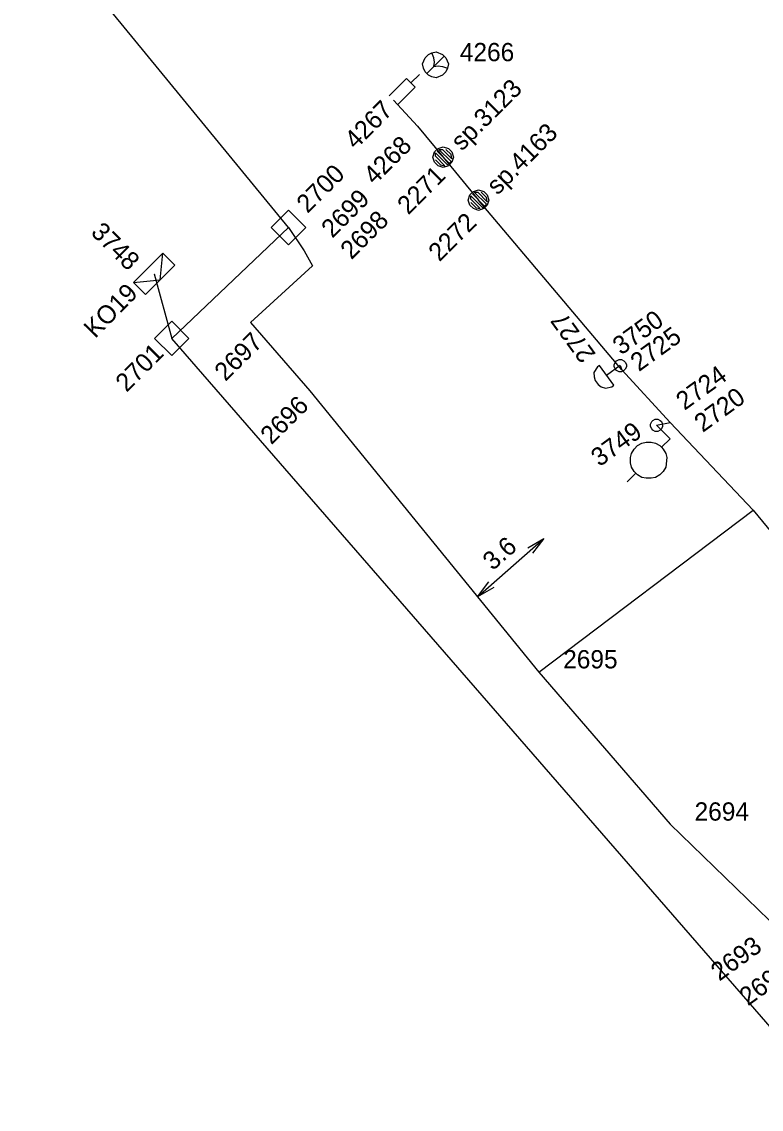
# Model space of a CAD drawing. Extents: x -535557 to -534097, y -1142175 to -1136716.
# Drawn here: x -535102.29 to -535071.96, y -1138807.65 to -1138763 of the extents above; entities that cross this region are included whole.
import ezdxf

# ---------------------------------------------------------------- set-up
doc = ezdxf.new("R2010")
doc.units = 0
doc.layers.add('Default', color=7, linetype='Continuous')
doc.layers.add('SS_SZDC', color=7, linetype='Continuous')

# ---------------------------------------------------------------- blocks, each defined once
blk = doc.blocks.new('POINT_DISPLAY')
at = {"layer": 'Default'}
blk.add_line((0, 0), (0, 0), dxfattribs=at)

msp = doc.modelspace()

# ---------------------------------------------------------------- linework, layer by layer
at = {"layer": 'SS_SZDC'}
for p, q in [((-535091.35, -1138771.45), (-535102.289, -1138758.09)), ((-535085.461, -1138764.275), (-535085.284, -1138764.239)), ((-535085.284, -1138764.239), (-535085.037, -1138764.345)), ((-535085.85, -1138764.734), (-535085.744, -1138764.487)), ((-535085.744, -1138764.487), (-535085.602, -1138764.345)), ((-535084.966, -1138764.416), (-535085.673, -1138765.123)), ((-535085.602, -1138764.345), (-535085.461, -1138764.275)), ((-535085.39, -1138764.487), (-535085.461, -1138764.275)), ((-535085.355, -1138764.663), (-535085.39, -1138764.487)), ((-535085.39, -1138764.84), (-535085.355, -1138764.663)), ((-535085.037, -1138764.345), (-535084.895, -1138764.487)), ((-535084.895, -1138764.487), (-535084.789, -1138764.734)), ((-535085.814, -1138764.911), (-535085.85, -1138764.734)), ((-535085.744, -1138765.052), (-535085.814, -1138764.911)), ((-535085.602, -1138765.194), (-535085.744, -1138765.052)), ((-535085.39, -1138764.84), (-535085.213, -1138764.805)), ((-535085.213, -1138764.805), (-535085.037, -1138764.84)), ((-535085.037, -1138764.84), (-535084.825, -1138764.911)), ((-535084.895, -1138765.052), (-535085.037, -1138765.194)), ((-535084.825, -1138764.911), (-535084.895, -1138765.052)), ((-535084.789, -1138764.734), (-535084.825, -1138764.911)), ((-535087.216, -1138766.043), (-535086.509, -1138765.336)), ((-535086.509, -1138765.336), (-535086.156, -1138765.689)), ((-535086.332, -1138765.512), (-535085.979, -1138765.159)), ((-535085.461, -1138765.264), (-535085.602, -1138765.194)), ((-535085.284, -1138765.3), (-535085.461, -1138765.264)), ((-535085.037, -1138765.194), (-535085.284, -1138765.3)), ((-535086.156, -1138765.689), (-535086.863, -1138766.396)), ((-535086.06, -1138767.29), (-535087.039, -1138766.219)), ((-535086.06, -1138767.29), (-535085, -1138768.56)), ((-535085.353, -1138768.347), (-535085.212, -1138768.206)), ((-535085.212, -1138768.206), (-535085, -1138768.135)), ((-535084.681, -1138768.736), (-535085.176, -1138768.241)), ((-535085.176, -1138768.241), (-535085.035, -1138768.241)), ((-535085.035, -1138768.241), (-535084.646, -1138768.63)), ((-535085, -1138768.135), (-535084.787, -1138768.206)), ((-535084.681, -1138768.453), (-535084.893, -1138768.241)), ((-535084.787, -1138768.206), (-535084.646, -1138768.347)), ((-535085.424, -1138768.56), (-535085.353, -1138768.347)), ((-535085.353, -1138768.772), (-535085.424, -1138768.56)), ((-535085.318, -1138768.524), (-535085.318, -1138768.383)), ((-535085.318, -1138768.383), (-535084.823, -1138768.878)), ((-535084.929, -1138768.913), (-535085.318, -1138768.524)), ((-535085.318, -1138768.666), (-535085.106, -1138768.878)), ((-535084.752, -1138768.807), (-535085.247, -1138768.312)), ((-535085, -1138768.56), (-535083.55, -1138770.32)), ((-535084.646, -1138768.63), (-535084.681, -1138768.453)), ((-535084.646, -1138768.347), (-535084.575, -1138768.56)), ((-535084.575, -1138768.56), (-535084.646, -1138768.772)), ((-535085.212, -1138768.913), (-535085.353, -1138768.772)), ((-535085, -1138768.984), (-535085.212, -1138768.913)), ((-535085.106, -1138768.878), (-535084.929, -1138768.913)), ((-535084.787, -1138768.913), (-535085, -1138768.984)), ((-535084.823, -1138768.878), (-535084.681, -1138768.736)), ((-535084.646, -1138768.772), (-535084.787, -1138768.913)), ((-535083.903, -1138770.107), (-535083.762, -1138769.966)), ((-535083.762, -1138769.966), (-535083.55, -1138769.895)), ((-535083.231, -1138770.496), (-535083.726, -1138770.001)), ((-535083.726, -1138770.001), (-535083.585, -1138770.001)), ((-535083.585, -1138770.001), (-535083.196, -1138770.39)), ((-535083.55, -1138769.895), (-535083.337, -1138769.966)), ((-535083.231, -1138770.213), (-535083.443, -1138770.001)), ((-535083.337, -1138769.966), (-535083.196, -1138770.107)), ((-535083.974, -1138770.32), (-535083.903, -1138770.107)), ((-535083.903, -1138770.532), (-535083.974, -1138770.32)), ((-535083.868, -1138770.284), (-535083.868, -1138770.143)), ((-535083.868, -1138770.143), (-535083.373, -1138770.638)), ((-535083.479, -1138770.673), (-535083.868, -1138770.284)), ((-535083.868, -1138770.426), (-535083.656, -1138770.638)), ((-535083.302, -1138770.567), (-535083.797, -1138770.072)), ((-535077.68, -1138777.29), (-535083.55, -1138770.32)), ((-535083.373, -1138770.638), (-535083.231, -1138770.496)), ((-535083.196, -1138770.39), (-535083.231, -1138770.213)), ((-535083.196, -1138770.107), (-535083.125, -1138770.32)), ((-535083.125, -1138770.32), (-535083.196, -1138770.532)), ((-535091.35, -1138770.742), (-535092.057, -1138771.45)), ((-535090.642, -1138771.45), (-535091.35, -1138770.742)), ((-535083.762, -1138770.673), (-535083.903, -1138770.532)), ((-535083.55, -1138770.744), (-535083.762, -1138770.673)), ((-535083.656, -1138770.638), (-535083.479, -1138770.673)), ((-535083.337, -1138770.673), (-535083.55, -1138770.744)), ((-535083.196, -1138770.532), (-535083.337, -1138770.673)), ((-535096.14, -1138776), (-535091.35, -1138771.45)), ((-535092.057, -1138771.45), (-535091.35, -1138772.157)), ((-535091.35, -1138771.45), (-535090.71, -1138772.409)), ((-535091.35, -1138772.157), (-535090.642, -1138771.45)), ((-535097.708, -1138773.703), (-535096.506, -1138772.501)), ((-535096.612, -1138773.597), (-535096.506, -1138772.501)), ((-535096.506, -1138772.501), (-535096.011, -1138772.996)), ((-535090.71, -1138772.409), (-535090.359, -1138773.02)), ((-535096.011, -1138772.996), (-535097.213, -1138774.198)), ((-535090.359, -1138773.02), (-535092.909, -1138775.35)), ((-535097.708, -1138773.703), (-535096.612, -1138773.597)), ((-535096.859, -1138773.35), (-535096.14, -1138776)), ((-535097.213, -1138774.198), (-535097.708, -1138773.703)), ((-535096.14, -1138775.292), (-535096.847, -1138776)), ((-535095.432, -1138776), (-535096.14, -1138775.292)), ((-535092.909, -1138775.35), (-535090.47, -1138778.149)), ((-535096.847, -1138776), (-535096.14, -1138776.707)), ((-535067.31, -1138809.2), (-535096.14, -1138776)), ((-535096.14, -1138776.707), (-535095.432, -1138776)), ((-535078.674, -1138777.174), (-535078.818, -1138777.402)), ((-535078.593, -1138777.115), (-535078.674, -1138777.174)), ((-535078.006, -1138777.924), (-535078.593, -1138777.115)), ((-535077.739, -1138777.12), (-535078.3, -1138777.52)), ((-535077.989, -1138777.07), (-535077.939, -1138776.97)), ((-535077.989, -1138777.17), (-535077.989, -1138777.07)), ((-535077.939, -1138777.27), (-535077.989, -1138777.17)), ((-535077.939, -1138776.97), (-535077.889, -1138776.92)), ((-535077.889, -1138776.92), (-535077.789, -1138776.87)), ((-535077.789, -1138776.87), (-535077.689, -1138776.87)), ((-535077.739, -1138777.12), (-535077.68, -1138777.29)), ((-535077.689, -1138776.87), (-535077.589, -1138776.92)), ((-535077.589, -1138776.92), (-535077.539, -1138776.97)), ((-535077.539, -1138776.97), (-535077.489, -1138777.07)), ((-535077.489, -1138777.17), (-535077.539, -1138777.27)), ((-535077.489, -1138777.07), (-535077.489, -1138777.17)), ((-535078.818, -1138777.402), (-535078.811, -1138777.582)), ((-535078.811, -1138777.582), (-535078.763, -1138777.732)), ((-535077.889, -1138777.32), (-535077.939, -1138777.27)), ((-535077.789, -1138777.37), (-535077.889, -1138777.32)), ((-535077.689, -1138777.37), (-535077.789, -1138777.37)), ((-535077.589, -1138777.32), (-535077.689, -1138777.37)), ((-535075.689, -1138779.45), (-535077.68, -1138777.29)), ((-535077.539, -1138777.27), (-535077.589, -1138777.32)), ((-535078.763, -1138777.732), (-535078.645, -1138777.894)), ((-535078.645, -1138777.894), (-535078.517, -1138777.986)), ((-535078.517, -1138777.986), (-535078.348, -1138778.049)), ((-535078.348, -1138778.049), (-535078.087, -1138777.983)), ((-535078.087, -1138777.983), (-535078.006, -1138777.924)), ((-535090.47, -1138778.149), (-535081.079, -1138789.7)), ((-535076.5, -1138779.519), (-535076.449, -1138779.419)), ((-535076.449, -1138779.419), (-535076.4, -1138779.369)), ((-535076.4, -1138779.369), (-535076.3, -1138779.319)), ((-535076.3, -1138779.319), (-535076.199, -1138779.319)), ((-535076.199, -1138779.319), (-535076.099, -1138779.369)), ((-535076.099, -1138779.369), (-535076.05, -1138779.419)), ((-535076.05, -1138779.419), (-535076, -1138779.519)), ((-535076.5, -1138779.619), (-535076.5, -1138779.519)), ((-535076.449, -1138779.719), (-535076.5, -1138779.619)), ((-535076.4, -1138779.769), (-535076.449, -1138779.719)), ((-535076.3, -1138779.819), (-535076.4, -1138779.769)), ((-535076.199, -1138779.819), (-535076.3, -1138779.819)), ((-535076.25, -1138779.569), (-535075.689, -1138779.45)), ((-535076.25, -1138779.569), (-535075.689, -1138780.12)), ((-535076.099, -1138779.769), (-535076.199, -1138779.819)), ((-535076.05, -1138779.719), (-535076.099, -1138779.769)), ((-535076, -1138779.619), (-535076.05, -1138779.719)), ((-535076, -1138779.519), (-535076, -1138779.619)), ((-535072.289, -1138783.059), (-535075.689, -1138779.45)), ((-535077.033, -1138780.402), (-535076.856, -1138780.296)), ((-535076.856, -1138780.296), (-535076.679, -1138780.261)), ((-535076.679, -1138780.261), (-535076.467, -1138780.261)), ((-535076.467, -1138780.261), (-535076.291, -1138780.296)), ((-535076.291, -1138780.296), (-535076.114, -1138780.402)), ((-535075.689, -1138780.12), (-535076.043, -1138780.473)), ((-535077.316, -1138780.897), (-535077.28, -1138780.721)), ((-535077.28, -1138780.721), (-535077.174, -1138780.544)), ((-535077.174, -1138780.544), (-535077.033, -1138780.402)), ((-535076.114, -1138780.402), (-535076.043, -1138780.473)), ((-535076.043, -1138780.473), (-535075.972, -1138780.544)), ((-535075.972, -1138780.544), (-535075.866, -1138780.721)), ((-535075.866, -1138780.721), (-535075.831, -1138780.897)), ((-535077.316, -1138781.109), (-535077.316, -1138780.897)), ((-535077.28, -1138781.286), (-535077.316, -1138781.109)), ((-535075.831, -1138780.897), (-535075.866, -1138781.286)), ((-535077.104, -1138781.534), (-535077.457, -1138781.887)), ((-535077.174, -1138781.463), (-535077.28, -1138781.286)), ((-535077.033, -1138781.604), (-535077.174, -1138781.463)), ((-535076.856, -1138781.71), (-535077.033, -1138781.604)), ((-535076.114, -1138781.604), (-535076.291, -1138781.71)), ((-535075.972, -1138781.463), (-535076.114, -1138781.604)), ((-535075.866, -1138781.286), (-535075.972, -1138781.463)), ((-535076.679, -1138781.746), (-535076.856, -1138781.71)), ((-535076.467, -1138781.746), (-535076.679, -1138781.746)), ((-535076.291, -1138781.71), (-535076.467, -1138781.746)), ((-535081.079, -1138789.7), (-535072.289, -1138783.059)), ((-535072.289, -1138783.059), (-535070.36, -1138785.4)), ((-535083.591, -1138786.61), (-535080.872, -1138784.215)), ((-535081.534, -1138784.598), (-535080.872, -1138784.215)), ((-535080.872, -1138784.215), (-535081.336, -1138784.823)), ((-535083.591, -1138786.61), (-535083.128, -1138786.002)), ((-535082.929, -1138786.227), (-535083.591, -1138786.61)), ((-535081.079, -1138789.7), (-535075.689, -1138795.95)), ((-535075.689, -1138795.95), (-535071.18, -1138800.329))]:
    msp.add_line(p, q, dxfattribs=at)

# ---------------------------------------------------------------- block references
for p in [(-535085.319, -1138764.77), (-535087.039, -1138766.219), (-535086.06, -1138767.29), (-535085, -1138768.56), (-535083.55, -1138770.32), (-535091.35, -1138771.45), (-535090.71, -1138772.409), (-535090.359, -1138773.02), (-535096.859, -1138773.35), (-535092.909, -1138775.35), (-535096.14, -1138776), (-535077.739, -1138777.12), (-535077.739, -1138777.12), (-535078.3, -1138777.52), (-535077.68, -1138777.29), (-535090.47, -1138778.149), (-535076.25, -1138779.569), (-535076.25, -1138779.569), (-535075.689, -1138779.45), (-535075.689, -1138780.12), (-535072.289, -1138783.059), (-535081.079, -1138789.7), (-535075.689, -1138795.95)]:
    msp.add_blockref('POINT_DISPLAY', p, dxfattribs=at)

# ---------------------------------------------------------------- texts
for s, p in [('4266', (-535084.319, -1138764.62)), ('2695', (-535080.079, -1138789.55)), ('2694', (-535074.689, -1138795.8))]:
    msp.add_text(s, height=0.75, dxfattribs=at).set_placement(p)
for s, rotation, p in [('sp.3123', 45, (-535084.237, -1138768.335)), ('4267', 45, (-535088.593, -1138768.272)), ('sp.4163', 45, (-535082.774, -1138770.147)), ('4268', 45, (-535087.819, -1138769.726)), ('2700', 45, (-535090.564, -1138770.895)), ('2271', 45, (-535086.432, -1138770.955)), ('2699', 45, (-535089.547, -1138771.912)), ('2698', 45, (-535088.765, -1138772.792)), ('2272', 45, (-535085.155, -1138772.885)), ('3748', 315, (-535099.493, -1138771.688)), ('KO19', 45.3757, (-535099.282, -1138776.029)), ('3750', 36, (-535077.702, -1138776.711)), ('2727', 126, (-535078.717, -1138776.649)), ('2697', 45, (-535093.93, -1138777.795)), ('2725', 36, (-535076.973, -1138777.386)), ('2701', 45, (-535097.989, -1138778.241)), ('2724', 36, (-535075.101, -1138778.978)), ('2720', 36, (-535074.353, -1138779.883)), ('2696', 45, (-535092.046, -1138780.398)), ('3749', 36, (-535078.589, -1138781.295)), ('3.6', 41.375, (-535082.969, -1138785.562)), ('2693', 36, (-535073.673, -1138802.413)), ('2692', 36, (-535072.502, -1138803.429))]:
    msp.add_text(s, height=0.75, rotation=rotation, dxfattribs=at).set_placement(p)

doc.saveas('drawing.dxf')
